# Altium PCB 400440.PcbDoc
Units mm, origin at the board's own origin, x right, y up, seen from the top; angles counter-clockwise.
Board outline 44.17 x 77.19 mm, 2 copper layers (Top Layer, Bottom Layer), stack 1.271 mm thick; 54 components, 42 nets, 195 pads, 342 vias.
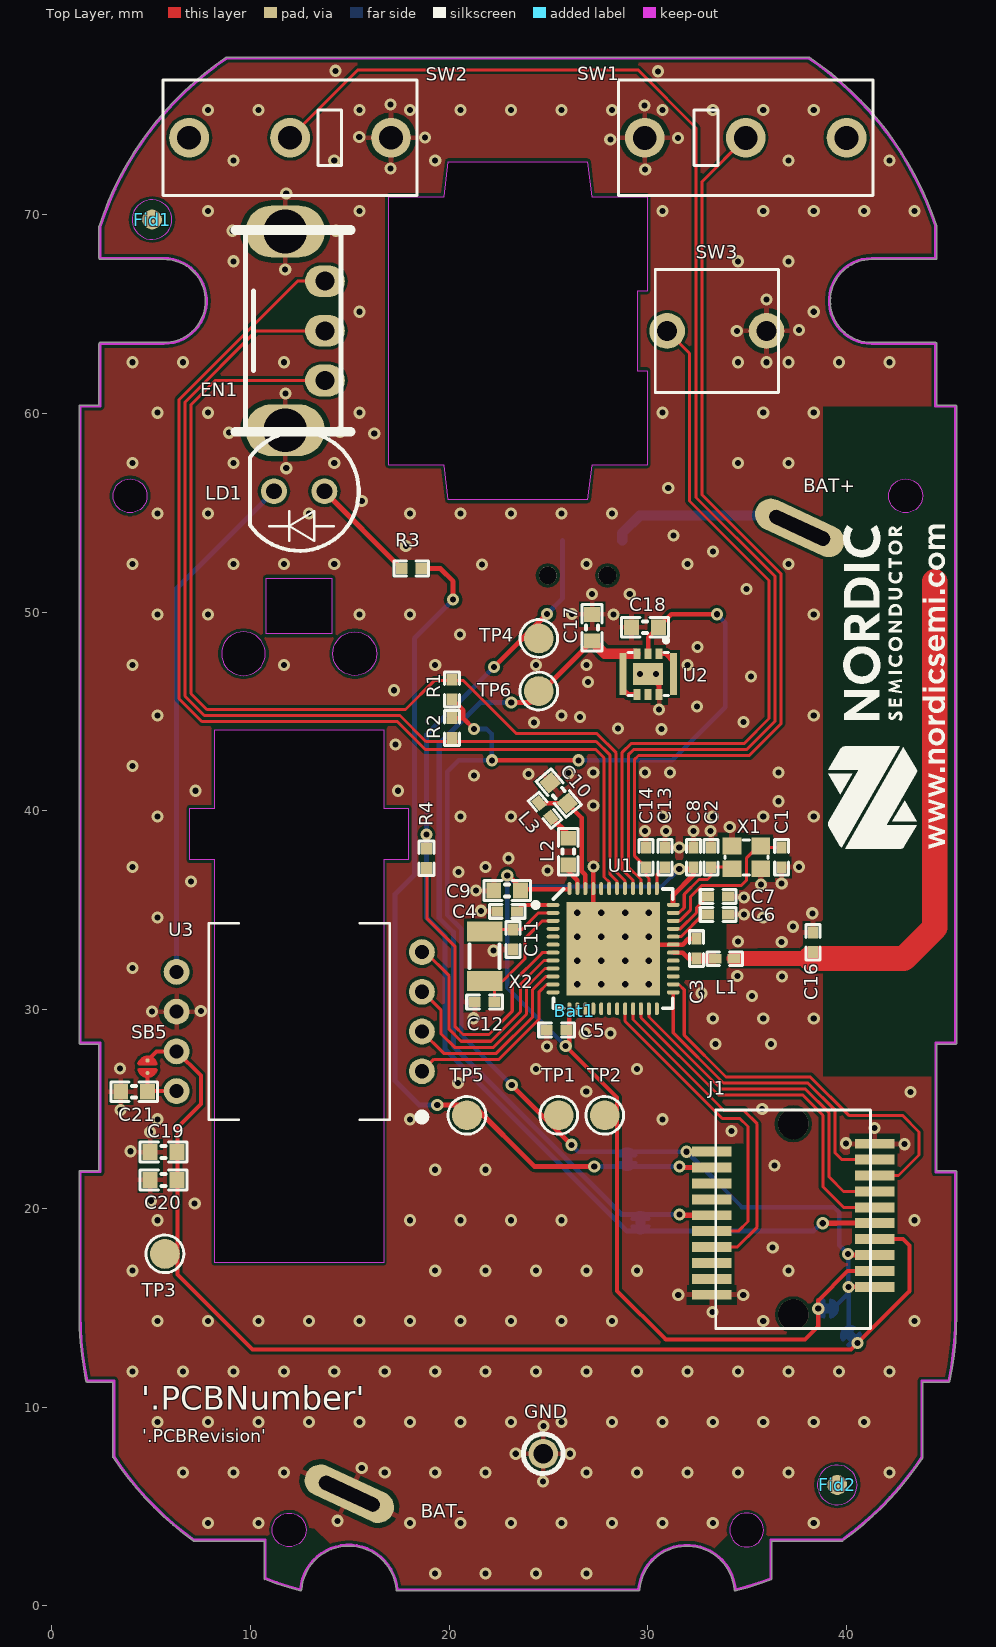
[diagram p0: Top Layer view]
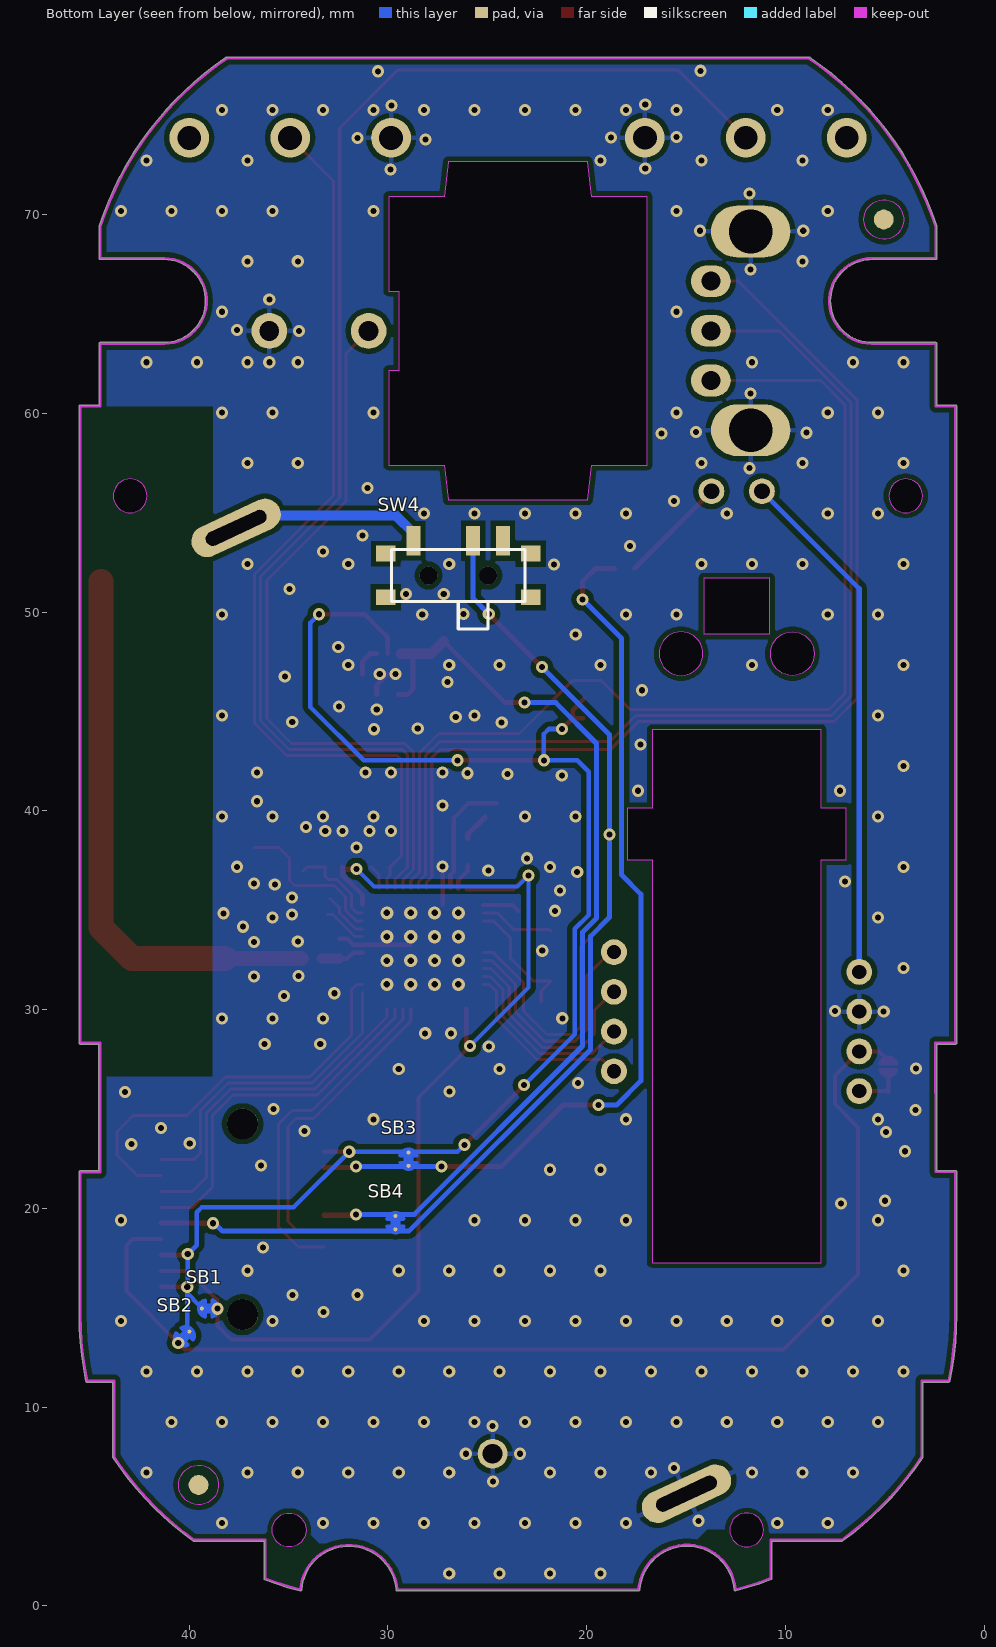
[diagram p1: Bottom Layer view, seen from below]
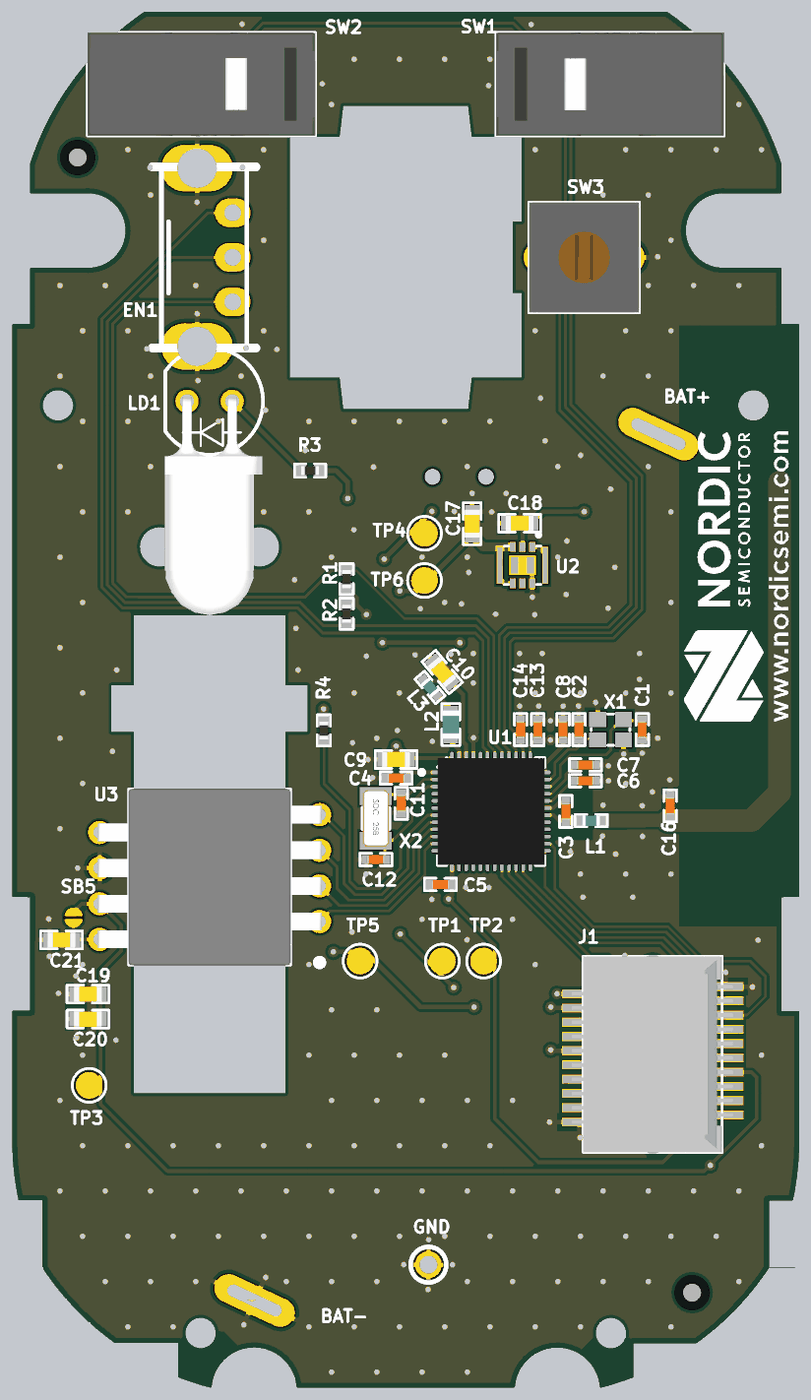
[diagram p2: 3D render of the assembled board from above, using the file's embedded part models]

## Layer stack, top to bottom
Top Solder: solder mask 0.0102, Solder Resist, Dk 3.5
Top Layer: signal copper 0.0356
Dielectric1: core 1.2, FR-4, Dk 4.8
Bottom Layer: signal copper 0.0356
Bottom Solder: solder mask 0.0102, Solder Resist, Dk 3.5

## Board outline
3.077,7.489 3.077,11.259 1.784,11.259 cw(c1.784,11.323) 1.721,11.31 cw(c17.452,14.626) 1.375,14.626 1.375,21.831 cw(c1.439,21.831) 1.439,21.895 2.376,21.895 2.376,28.266 1.445,28.266 cw(c1.445,28.33) 1.393,28.292 cw(c1.439,28.336) 1.375,28.336 1.375,60.362 cw(c1.439,60.362) 1.439,60.425 2.376,60.425 2.376,63.514 cw(c2.44,63.514) 2.44,63.578 5.643,63.578 ccw(c5.643,65.666) 7.731,65.666 ccw(c5.643,65.666) 5.616,67.753 ccw(c5.643,65.666) 5.616,67.753 cw(c5.615,67.817) 5.615,67.753 2.44,67.753 cw(c2.44,67.817) 2.376,67.817 2.376,69.412 cw(c2.44,69.412) 2.379,69.432 cw(c17.952,64.365) 8.775,77.928 cw(c8.811,77.875) 8.811,77.939 38.103,77.939 cw(c38.103,77.875) 38.139,77.928 cw(c28.961,64.365) 44.534,69.432 cw(c44.473,69.412) 44.537,69.412 44.537,67.817 cw(c44.473,67.817) 44.473,67.753 41.271,67.753 cw(c41.271,67.817) 41.27,67.753 ccw(c41.271,65.666) 41.271,63.578 44.473,63.578 cw(c44.473,63.514) 44.537,63.514 44.537,60.425 45.474,60.425 cw(c45.474,60.362) 45.526,60.399 ccw(c45.479,60.355) 45.526,60.399 cw(c45.479,60.355) 45.543,60.355 45.543,28.33 cw(c45.479,28.33) 45.479,28.266 44.542,28.266 44.542,21.889 45.479,21.889 cw(c45.479,21.825) 45.543,21.825 45.543,14.619 cw(c29.467,14.619) 45.198,11.303 cw(c45.135,11.317) 45.135,11.253 43.842,11.253 43.842,7.483 cw(c43.778,7.483) 43.831,7.447 cw(c30.425,16.321) 39.797,3.258 cw(c39.76,3.31) 39.76,3.246 36.236,3.246 36.236,1.375 cw(c36.172,1.375) 36.195,1.315 cw(c30.425,16.321) 34.428,0.75 cw(c34.412,0.812) 34.412,0.748 cw(c34.412,0.812) 34.348,0.807 ccw(c31.969,0.608) 29.589,0.808 cw(c29.525,0.814) 29.515,0.751 17.394,0.751 cw(c17.394,0.815) 17.33,0.81 ccw(c14.95,0.615) 12.57,0.814 ccw(c14.95,0.615) 12.57,0.813 12.57,0.814 cw(c12.507,0.819) 12.507,0.755 cw(c12.507,0.819) 12.491,0.757 cw(c16.493,16.327) 10.724,1.321 cw(c10.747,1.381) 10.683,1.381 10.683,3.253 7.159,3.253 cw(c7.159,3.317) 7.122,3.265 cw(c16.493,16.327) 3.087,7.454 cw(c3.141,7.489)
cut-out: 34.12,3.811 ccw(c34.971,3.811) 34.971,2.96 ccw(c34.971,3.811) 35.822,3.811 ccw(c34.971,3.811) 34.971,4.661 ccw(c34.971,3.811)
cut-out: 11.948,2.966 cw(c11.948,3.817) 11.097,3.817 cw(c11.948,3.817) 11.948,4.668 cw(c11.948,3.817) 12.798,3.817 cw(c11.948,3.817)
cut-out: 42.972,55.007 cw(c42.972,55.858) 42.121,55.858 cw(c42.972,55.858) 42.972,56.709 cw(c42.972,55.858) 43.823,55.858 cw(c42.972,55.858)
cut-out: 3.941,55.007 cw(c3.941,55.858) 3.091,55.858 cw(c3.941,55.858) 3.941,56.709 cw(c3.941,55.858) 4.792,55.858 cw(c3.941,55.858)
cut-out: 15.25,46.816 cw(c15.25,47.917) 14.149,47.917 cw(c15.25,47.917) 15.25,49.018 cw(c15.25,47.917) 16.351,47.917 cw(c15.25,47.917)
cut-out: 9.646,46.816 ccw(c9.646,47.917) 10.747,47.917 ccw(c9.646,47.917) 9.646,49.018 ccw(c9.646,47.917) 8.545,47.917 ccw(c9.646,47.917)
cut-out: 10.797,48.913 10.797,51.715 14.099,51.715 14.099,48.913
cut-out: 16.701,44.089 16.701,40.146 17.952,40.146 17.952,37.544 16.701,37.544 16.701,17.268 8.195,17.268 8.195,37.544 6.944,37.544 6.944,40.146 8.195,40.146 8.195,44.089
cut-out: 29.962,70.92 29.962,66.166 29.461,66.166 29.461,62.163 29.962,62.163 29.962,57.409 27.166,57.409 26.959,55.658 19.954,55.658 19.748,57.409 16.952,57.409 16.952,70.92 19.748,70.92 19.954,72.671 26.959,72.671 27.166,70.92

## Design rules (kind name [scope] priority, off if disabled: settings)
Clearance ANT_Clerance [InNet('ANT')] p1: gap=0.127 ignorepadtopadclearanceinfootprint=FALSE except(0: Arc-Hole Track-Hole SMDPad-Hole THPad-Hole Via-Hole Fill-Hole Poly-Hole Region-Hole Text-Hole)
Clearance Polygon_Clearance [(InNamedPolygon('Top_Layer-GND')) or (InNamedPolygon('Bottom_Layer-GND'))] p2: gap=0.254 ignorepadtopadclearanceinfootprint=FALSE except(0: Arc-Hole Track-Hole SMDPad-Hole THPad-Hole Via-Hole Fill-Hole Poly-Hole Region-Hole Text-Hole)
Clearance [All] p3: gap=0.152 ignorepadtopadclearanceinfootprint=FALSE except(0: Arc-Hole Track-Hole SMDPad-Hole THPad-Hole Via-Hole Fill-Hole Poly-Hole Region-Hole Text-Hole)
ComponentClearance [All] p1 off: gap=0.254 collisioncheckmode=3 verticalgap=0.254 showdistances=FALSE
DiffPairsRouting [All] p1: maxlimit=0.15 minlimit=0.15 mostfreqgap=0.15 toplayer_minwidth=0.381 toplayer_maxwidth=0.381 toplayer_prefwidth=0.381 bottomlayer_minwidth=0.381 bottomlayer_maxwidth=0.381 bottomlayer_prefwidth=0.381 maxuncoupledlength=12.7
FabricationTestPointUsage TestPointUsage [All] p1: valid=0 allowmultiple=FALSE
FabricationTestpoint Testpoint [All] p1: side=3 testpointundercomponent=TRUE minsize=1.016 maxsize=2.54 preferedsize=1.524 minholesize=0 maxholesize=1.016 preferedholesize=0.813 testpointgrid=0.025 allowsidetop=TRUE allowsidebottom=TRUE usegrid=TRUE gridtolerance=0
Height [All] p1 off: minheight=0 maxheight=25.4 prefheight=12.7
HoleSize [All] p1: absolutevalues=TRUE maxlimit=5 minlimit=0.305 maxpercent=80.000 minpercent=20.000
MinimumAnnularRing [All] p1 off: minimumring=0.152
PolygonConnect PolygonConnect_1 [isVia and innet(gnd)] p1: connectstyle=Direct reliefconductorwidth=0.254 reliefentries=4 polygonreliefangle="90 Angle" airgapwidth=0.254
PolygonConnect [All] p2: connectstyle=Relief reliefconductorwidth=0.254 reliefentries=4 polygonreliefangle="90 Angle" airgapwidth=0.254
RoutingVias [All] p1: holewidth=0.305 width=0.61 viastyle="Through Hole" minholewidth=0.305 minwidth=0.61 maxholewidth=0.711 maxwidth=1.27
SilkToSolderMaskClearance SilkscreenOverComponentPads [IsPad] p1: minsilkscreentomaskgap=0.254 clearancetoexposedcopper=TRUE
SolderMaskExpansion [All] p1: expansion=0.076 istentingtop=FALSE
Width [All] p1: maxlimit=2.54 minlimit=0.152 preferedwidth=0.152
23 further rules are at their usual default settings.

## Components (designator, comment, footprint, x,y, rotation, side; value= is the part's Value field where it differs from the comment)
Bat1 "" MORFFLUOA_Battery_Spring 26.308,29.943 r0 top locked
C1 "12pF" CAPC1005X04L 36.736,37.668 r270 top
C2 "12pF" CAPC1005X04L 33.18,37.668 r90 top
C3 "0.8pF" CAPC1005X04L 32.443,33.071 r270 top
C4 "100nF" CAPC1005X04L 22.918,34.95 r180 top
C5 "100nF" CAPC1005X04L 25.407,28.981 r180 top
C6 "N.C." CAPC1005X04L 33.535,34.798 r180 top
C7 "100pF" CAPC1005X04L 33.535,35.687 r0 top
C8 "100nF" CAPC1005X04L 32.291,37.668 r90 top
C9 "4.7µF" CAPC1608X06L 22.918,35.992 r180 top
C10 "1.0µF" CAPC1608X06L 25.51,40.899 r310 top
C11 "12pF" CAPC1005X04L 23.207,33.528 r270 top
C12 "12pF" CAPC1005X04L 21.785,30.378 r180 top
C13 "12pF" CAPC1005X04L 30.868,37.668 r90 top
C14 "12pF" CAPC1005X04L 29.903,37.668 r90 top
C16 "1.2pF" CAPC1005X04L 38.304,33.392 r90 top
C17 "10µF" CAPC1608X06L 27.19,49.222 r270 top
C18 "10µF" CAPC1608X06L 29.851,49.247 r0 top
C19 "10µF" CAPC1608X06L 5.627,22.831 r0 top
C20 "100nF" CAPC1608X06L 5.627,21.429 r0 top
C21 "4.7µF" CAPC1608X06L 4.145,25.869 r0 top
EN1 "Scroll wheel encoder" M01_Scroll_Wheel_Encoder 13.748,64.164 r270 top locked
Fid1 "Fiducial mark" Fiducial 5.048,69.766 r0 top
Fid2 "Fiducial mark" Fiducial 39.53,6.082 r0 top
GND "TP" TESTPAD-TH 24.733,7.649 r0 top
J1 "Card Edge, 0.8mm" 10056847-101LF 37.316,19.453 r90 top
L1 "3.9nH" INDC1005X04L 33.866,32.563 r0 top
L2 "10µH" INDC1608X06L 25.992,37.953 r270 top
L3 "15nH" INDC1005X04L 24.824,40.035 r310 top
LD1 "LED" LED_5MM_RA 12.452,56.09 r180 top locked
R1 "1M0" RESC1005X04L 20.136,46.111 r270 top
R2 "1M0" RESC1005X04L 20.136,44.17 r90 top
R3 "4R7" RESC1005X04L 18.093,52.202 r0 top
R4 "1k" RESC1005X04L 18.861,37.62 r270 top
SB1 "Solderbridge" Solderbridge_Shorted_Power 39.026,14.961 r180 bottom net-tie
SB2 "Solderbridge" Solderbridge_Shorted_Power 40.236,13.554 r315 bottom net-tie
SB3 "Solderbridge" Solderbridge_Shorted_Power 28.964,22.477 r270 bottom net-tie
SB4 "Solderbridge" Solderbridge_Shorted_Power 29.626,19.283 r90 bottom net-tie
SB5 "Solderbridge" Solderbridge 4.819,27.124 r270 top
SW1 "SPDT" D2F-F 29.842,73.875 r0 top locked
SW2 "SPDT" D2F-F 17.072,73.882 r180 top locked
SW3 "EVQ-P0E07K" EVQP0E07K 33.471,64.157 r0 top locked
SW4 "CUS-12TB" CUS-12B 26.462,51.853 r180 bottom locked
TP1 "Ø1.5mm,SMD" TP_SMD_Ø1.5mm 25.513,24.683 r0 top
TP2 "Ø1.5mm,SMD" TP_SMD_Ø1.5mm 27.828,24.683 r0 top
TP3 "Ø1.5mm,SMD" TP_SMD_Ø1.5mm 5.694,17.711 r0 top
TP4 "Ø1.5mm,SMD" TP_SMD_Ø1.5mm 24.512,48.683 r0 top
TP5 "Ø1.5mm,SMD" TP_SMD_Ø1.5mm 20.897,24.683 r0 top
TP6 "Ø1.5mm,SMD" TP_SMD_Ø1.5mm 24.512,46.033 r0 top
U1 "nRF52832-QFAAE0" QFN40P600X600X90-48N 28.252,33.071 r0 top locked
U2 "XCL101" CL-2025 30.014,46.889 r270 top
U3 "PAW3212" PAW3212DB-TJDT 12.454,28.899 r90 top locked
X1 "32MHz" BT-XTAL_2016 34.958,37.668 r180 top
X2 "32.768kHz" XTAL_3215 21.785,32.69 r270 top

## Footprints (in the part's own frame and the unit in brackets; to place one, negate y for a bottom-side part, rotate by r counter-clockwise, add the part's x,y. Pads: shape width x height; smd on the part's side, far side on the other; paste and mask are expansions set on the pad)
10056847-101LF [mm]
  rect 0.5x2 smd paste-0.05 mask+0.025: 1(-3.4,-4.1) 2(-2.6,-4.1) 3(-1.8,-4.1) 4(-1,-4.1) 5(-0.2,-4.1) 6(0.6,-4.1) 7(1.4,-4.1) 8(2.2,-4.1) 9(3,-4.1) 10(3.8,-4.1) 11(3.4,4.1) 12(2.6,4.1) 13(1.8,4.1) 14(1,4.1) 15(0.2,4.1) 16(-0.6,4.1) 17(-1.4,4.1) 18(-2.2,4.1) 19(-3,4.1) 20(-3.8,4.1)
  round 1.55 hole 1.55 unplated mask+0: ""(-4.8,0) ""(4.8,0)
  silkscreen extent -5.5,-3.9 5.5,3.9, body extent -5.5,-4.5 5.5,4.53, height 5.28
BT-XTAL_2016 [mm] "Crystal 2.0 x 1.6 mm"
  rect 0.95x0.85 smd: 1(-0.725,-0.575) 2(0.725,-0.575) 3(0.725,0.575) 4(-0.725,0.575)
  silkscreen extent -1.08,-0.88 1.08,0.88
CAPC1005X04L [mm] "Chip Capacitor, 2-Leads, Body 1.0x0.5mm, IPC High Density"
  rect 0.6x0.5 smd: 1(-0.5,0) 2(0.5,0)
  silkscreen extent -0.9,-0.35 0.9,0.35, body extent -0.51,-0.25 0.51,0.25, height 0.5
CAPC1608X06L [mm] "Chip Capacitor, 2-Leads, Body 1.6x0.8mm, IPC High Density"
  rect 0.75x0.8 smd: 1(-0.675,0) 2(0.675,0)
  silkscreen extent -1.17,-0.5 1.17,0.5, body extent -0.8,-0.43 0.8,0.43, height 0.8
CL-2025 [mm]
  rect 0.55x0.35 smd paste-0.025 mask+0.076: 1(-1.025,0.55) 2(-1.025,0) 3(-1.025,-0.55) 4(1.025,-0.55) 5(1.025,0) 6(1.025,0.55)
  rect 2.1x0.35 smd paste-0.038 mask+0.076: 7(0,1.275) 8(0,-1.275)
  rect 1.1x1.5 smd paste-5 mask+0.076: 9(0,0)
  silkscreen extent -1.8,-1.02 1.07,1.02, body extent -1,-1.25 1.01,1.25, height 1
CUS-12B [mm] "Slide Switches - SPDT, SMD, ON-ON"
  rect 1x0.8 smd: 0(-3.65,-1.1) 0(-3.65,1.1) 0(3.65,-1.1) 0(3.65,1.1)
  round 0.9 hole 0.9 unplated: 0(-1.5,0) 0(1.5,0)
  rect 0.7x1.5 smd: 1(2.25,1.75) 2(0.75,1.75) 3(-2.25,1.75)
  silkscreen extent -3.35,-2.7 3.35,1.3, body extent -3.85,-2.75 3.85,2.2, height 1.4
D2F-F [mm]
  round 2 hole 1.2: 1(10.16,0) 2(0,0) 3(5.08,0)
  silkscreen extent -1.32,-2.9 11.48,2.9, body extent -1.32,-2.9 11.48,2.9, height 7
EVQP0E07K [mm]
  round 1.8 hole 1: 1(-2.5,0) 2(2.5,0)
  silkscreen extent -3.1,-3.1 3.1,3.1, body extent -3.1,-3.1 3.1,3.1, height 7.5
Fiducial [mm] "Fiducial Mark"
  round 1 smd paste+0 mask+0.5: 0(0,0)
  round 1 smd far side paste+0 mask+0.5: 0(0,0)
  Top Layer keep-out circle w0.01: c0,0 r1
  Bottom Layer keep-out circle w0.01: c0,0 r1
INDC1005X04L [mm] "Chip Inductor, 2-Leads, Body 1.0x0.5mm, IPC High Density"
  rect 0.65x0.5 smd: 1(-0.475,0) 2(0.475,0)
  silkscreen extent -0.9,-0.35 0.9,0.35, body extent -0.5,-0.3 0.5,0.3, height 0.5
INDC1608X06L [mm] "Chip Inductor, 2-Leads, Body 1.6x0.8mm, IPC High Density"
  rect 0.75x0.8 smd: 1(-0.675,0) 2(0.675,0)
  silkscreen extent -1.18,-0.5 1.17,0.5, body extent -0.8,-0.48 0.8,0.48, height 0.8
LED_5MM_RA [mm]
  round 1.3 hole 0.8: 1(1.27,0) 2(-1.27,0)
  silkscreen extent -3,-3 2.48,3, body extent -2.95,-0.25 2.5,12, height 5.95
M01_Scroll_Wheel_Encoder [mm]
  oval 1.6x2 hole 0.95: 1(-2.5,0) 2(0,0) 3(2.5,0)
  oval 2.6x4 hole 2.2: 4(-5,-2) 5(5,-2)
  silkscreen extent -5.08,-4.5 5.08,1.3
MORFFLUOA_Battery_Spring [mm] "Edge Mount Battery Holder Suitable for 1xAAA"
  oval 4.8x1.6 hole 0.7 slot 3.3 at 155 deg rot 155: 1(11.333,24.304) 2(-11.333,-24.304)
PAW3212DB-TJDT [mm] "Ultra Low Power Wireless Mouse Sensor"
  round 1.3 hole 0.71: 1(-2,-6.172) 2(0,-6.172) 3(2,-6.172) 4(4,-6.172) 5(3,6.172) 6(1,6.172) 7(-1,6.172) 8(-3,6.172)
  silkscreen extent -4.55,-6.42 5.45,4.55, body extent -4.45,-6.3 5.45,6.3, height 3.18
QFN40P600X600X90-48N [mm] "QFN, 48-Leads, Body 6,0x6,0mm (max), Pitch 0,40mm, IPC Medium Density"
  oval 0.65x0.2 smd mask+0.05: 1(-3.025,2.2) 2(-3.025,1.8) 3(-3.025,1.4) 4(-3.025,1) 5(-3.025,0.6) 6(-3.025,0.2) 7(-3.025,-0.2) 8(-3.025,-0.6) 9(-3.025,-1) 10(-3.025,-1.4) 11(-3.025,-1.8) 12(-3.025,-2.2) 25(3.025,-2.2) 26(3.025,-1.8) 27(3.025,-1.4) 28(3.025,-1) 29(3.025,-0.6) 30(3.025,-0.2) 31(3.025,0.2) 32(3.025,0.6) 33(3.025,1) 34(3.025,1.4) 35(3.025,1.8) 36(3.025,2.2)
  oval 0.2x0.65 smd mask+0.05: 13(-2.2,-3.025) 14(-1.8,-3.025) 15(-1.4,-3.025) 16(-1,-3.025) 17(-0.6,-3.025) 18(-0.2,-3.025) 19(0.2,-3.025) 20(0.6,-3.025) 21(1,-3.025) 22(1.4,-3.025) 23(1.8,-3.025) 24(2.2,-3.025) 37(2.2,3.025) 38(1.8,3.025) 39(1.4,3.025) 40(1,3.025) 41(0.6,3.025) 42(0.2,3.025) 43(-0.2,3.025) 44(-0.6,3.025) 45(-1,3.025) 46(-1.4,3.025) 47(-1.8,3.025) 48(-2.2,3.025)
  rect 4.7x4.7 smd: 49(0,0)
  silkscreen extent -4.02,-3 3,3, body extent -3.02,-3.02 3.02,3.02, height 0.86
RESC1005X04L [mm] "Chip Resistor, 2-Leads, Body 1.0x0.5mm, IPC High Density"
  rect 0.6x0.55 smd: 1(-0.5,0) 2(0.5,0)
  silkscreen extent -0.87,-0.38 0.88,0.38, body extent -0.5,-0.25 0.5,0.25, height 0.3
Solderbridge [mm]
  round 0.2 smd paste-10: 1(-0.312,0) 2(0.312,0)
  Top Layer region: 0.077,0.432 0.152,0.505 0.271,0.467 0.335,0.424 0.409,0.351 0.462,0.292 0.521,0.193 0.549,0.099 0.544,-0.122 0.518,-0.193 0.434,-0.33 0.351,-0.411 0.259,-0.469 0.157,-0.5 0.107,-0.483 0.077,-0.43
  Top Layer region: -0.077,-0.432 -0.152,-0.505 -0.271,-0.467 -0.335,-0.424 -0.409,-0.351 -0.462,-0.292 -0.521,-0.193 -0.549,-0.099 -0.544,0.122 -0.518,0.193 -0.434,0.33 -0.351,0.411 -0.259,0.469 -0.157,0.5 -0.107,0.483 -0.077,0.43
  Top Layer lines w0.152: 0.153,-0.431 ccw(c0.042,0) 0.487,0.001 ccw(c0.042,0) 0.487,0.003 ccw(c0.042,0) 0.153,0.431 ; -0.153,-0.431 cw(c-0.042,0) -0.487,0 cw(c-0.042,0) -0.461,0.149 cw(c-0.042,0) -0.153,0.431
Solderbridge_Shorted_Power [mm]
  round 0.2 smd paste-10: 1(-0.338,0) 2(0.338,0)
  Top Layer region: -0.102,-0.432 -0.178,-0.505 -0.296,-0.467 -0.361,-0.424 -0.434,-0.351 -0.488,-0.292 -0.546,-0.193 -0.574,-0.099 -0.569,0.122 -0.544,0.193 -0.46,0.33 -0.376,0.411 -0.284,0.469 -0.183,0.5 -0.132,0.483 -0.102,0.43
  Top Layer region: 0.102,0.432 0.178,0.505 0.296,0.467 0.361,0.424 0.434,0.351 0.488,0.292 0.546,0.193 0.574,0.099 0.569,-0.122 0.544,-0.193 0.46,-0.33 0.376,-0.411 0.284,-0.469 0.183,-0.5 0.132,-0.483 0.102,-0.43
  Top Layer lines w0.152: 0.178,-0.431 ccw(c0.068,0) 0.178,0.431 ; -0.178,-0.431 cw(c-0.068,0) -0.178,0.431
  Top Layer lines w0.508: 0.338,0 -0.338,0
TESTPAD-TH [mm]
  round 1.5 hole 1: 1(0,0)
  silkscreen extent -1,-1 1,1
TP_SMD_Ø1.5mm [mm]
  round 1.5 smd paste-5: 1(0,0)
  silkscreen extent -0.95,-0.95 0.95,0.95
XTAL_3215 [mm] "XTAL SMD 3.2 x 1.5 mm"
  rect 1x1.8 smd: 1(-1.25,0) 2(1.25,0)
  silkscreen extent -0.6,-0.75 0.6,0.75, body extent -1.6,-0.75 1.6,0.75, height 0.81

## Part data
Bat1: library part "MORFFLOUA Battery Spring", "Battery Spring, 1xAA", Part number IPS=N.A.
C1 C2 C11 C12 C13 C14: library part C0402-12p, "Capacitor, NP0, ±2%"
C3: library part C0402-0.8p, "Capacitor, NP0, ±5%"
C4 C5 C8: library part C0402-100n, "Capacitor, X7R, ±10%"
C6: library part C0402-N.C., "Not mounted"
C7: library part C0402-100p, "Capacitor, NP0, ±5%"
C9: library part C0603-4µ7, "Capacitor, X5R, ±10%"
C10: library part C0603-1µ0, "Capacitor, X7R, ±10%"
C16: library part C0402-1.2p, "Capacitor, NP0, ±0.1pF", Manufacturer=N.A., Part number IPS=00000005410
C17 C18 C19: library part C0603-10µ, "Capacitor, X5R, ±20%", Part number IPS=00000007785
C20: library part C0603-100n, "Chip Cap 0603", Part number IPS=N.A.
C21: library part C0603-4µ7, "Capacitor, X5R, ±10%", Part number IPS=00000007783
EN1: library part "M01_Scroll_wheel_encoder, 9mm", "Scroll wheel encoder, 9mm", Part number IPS=N.A.
Fid1 Fid2: library part Fid-Mark, "Fiducial Mark", Part number IPS=N.A.
GND: library part "Testpoint TH", "Testpoint, through hole", Part number IPS=N.A.
J1: library part 10056847-101LF, "0.8mm pitch, dual edge, right angle, SMD, card edge connector", Manufacturer=FCI, Part number IPS=N.A., Supplier Part Number 1=609-4943-1-ND
L1: library part L0402-3n9, "High frequency chip inductor ±5%", Manufacturer=Murata, Manufacturer Part Number=LQP15MN3N9B02D, Supplier part number=490-1131-1-ND
L2: library part L0603-10µ, "Chip inductor, IDC,min = 50 mA, ±20%", 2nd source part number=178-6105, Manufacturer="Taiyo Yuden", Manufacturer Part Number=LBMF1608T100K, Supplier part number=587-1714-1-ND
L3: library part L0402-15n, "High frequency chip inductor ±10%", 2nd source part number=658-1328, Manufacturer="Taiyo Yuden", Manufacturer Part Number=HK100515NJ-T, Supplier part number=587-1521-1-ND
LD1: library part 7383M-RNW3-APSB, "LED, Red, 5mm, Vf=2.0", Manufacturer=Everlight, Part number IPS=N.A.
R1 R2: library part R0402-1M0, "Resistor, ±1%, 0.063W", Part number IPS=00000006807
R3: library part R0402-4R7, "Resistor, ±1%, 0.063W", Part number IPS=N.A.
R4: library part R0402-1k0, "Resistor, ±1%, 0.063W", Part number IPS=00000002218, Supplier Part Number 1=173-8850
SB1 SB2 SB3 SB4: library part "Solderbridge Shorted Power", "Shorted Solderbridge Power", Part number IPS=N.A.
SB5: Part number IPS=N.A.
SW1 SW2: library part D2F-F, "SWITCH SNAP ACTION SPDT 1A 125V", Manufacturer=Omron, Part number IPS=N.A., Supplier Part Number 1=SW503-ND
SW3: "Switch tactile, SPST-NO, 0.05A, 30V", Manufacturer="Panasonic - ECG", Part number IPS=N.A., Supplier Part Number 1=P10843S-ND
SW4: "Low-profile slide switch, SPDT, ON-ON", Manufacturer="Copal Electronics Inc", Part number IPS=N.A., Supplier Part Number 1=563-1102-1-ND
TP1 TP2 TP3 TP4 TP5 TP6: library part TP_SMD_Ø1.5MM, "1.0mm circular SMD testpad", Manufacturer="Nordic Semiconductor", Part number IPS=N.A.
U1: "Multi-protocol Bluetooth Low Energy, ANT and 2.4GHz proprietary system-on-chip", Manufacturer="Nordic Semiconductor", Part number IPS=N.A.
U2: library part XCL101A211ER-G, "Inductor Built-in Step-up “micro DC/DC” Converter, VOUT=2.1V, 100mA", Manufacturer="Torex Semiconductor", Part number IPS=N.A., Supplier Part Number 1=893-1206-1-ND
U3: library part PAW3212DB-TJDT, "Ultra Low Power Wireless Mouse Sensor", Manufacturer="Pixart Imaging inc", Part number IPS=N.A.
X1: library part XTAL_SMD2016_32MHz_8pF_General, "XTAL SMD 2016, 32MHz, Cl=8pF, Total Tol: ±40ppm"
X2: library part XTAL_SMD3215_32.768kHz_9pF_General, "XTAL SMD 3215, 32.768kHz, Cl=9pF, Total Tol: ±50ppm"

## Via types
v1: diameter 0.61, hole 0.305, Top Layer to Bottom Layer, tented both sides, 326 vias
v2: diameter 0.66, hole 0.33, Top Layer to Bottom Layer, tented both sides, 16 vias

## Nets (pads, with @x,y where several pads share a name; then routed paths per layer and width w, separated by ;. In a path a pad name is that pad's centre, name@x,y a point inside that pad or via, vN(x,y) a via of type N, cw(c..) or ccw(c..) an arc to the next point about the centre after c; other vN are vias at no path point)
ANT: C16.1 L1.2 | length 28.3
  Top Layer w0.762: L1.2@34.349,32.569 35.508,32.57 36.508,32.572 38.304,32.573
  Top Layer w1.27: 38.19,32.573 42.879,32.573 44.439,34.132 44.439,51.554
BAT+: Bat1.1 SW4.3 | length 9.9
  Bottom Layer w0.508: SW4.3 28.712,53.985 29.591,54.864 37.023,54.864 Bat1.1@37.641,54.246
DEC1: C4.1 U1.1 | length 1.9
  Top Layer w0.203: C4.1@23.422,34.97 23.723,35.271 U1.1
DEC2: C6.2 U1.32 | length 2.2
  Top Layer w0.152: U1.32 31.663,33.671 32.79,34.798 C6.2@33.053,34.798
DEC3: C7.1 U1.33 | length 2.4
  Top Layer w0.152: U1.33 31.632,34.071 32.443,34.882 32.443,35.133 C7.1@32.927,35.617
DEC4: C10.2 L3.1 U1.46 | length 6
  Top Layer w0.229: L3.1 C10.2@25.926,40.399 ; C10.2 26.677,39.648 26.677,36.962 26.852,36.787 U1.46@26.852,36.126
GND: Bat1.2 C1.2 C2.2 C3.1 C4.2 C5.2 C6.1 C7.2 C8.2 C9.2 C10.1 C11.2 C12.2 C13.2 C14.2 C16.2 C17.1 C18.1 C19.1 C20.1 C21.1 EN1.4 EN1.5 GND.1 J1.10 J1.20 SW1.2 SW2.2 SW3.2 U1.31 U1.45 U1.49 U2.6 U2.9 U3.6 X1.2 X1.4 | length 6.9
  Top Layer w0.229: U1.49@27.252,35.271 U1.45 v1@27.252,37.211 ; U1.49@28.87,33.274 31.751,33.274 32.038,33.561 C3.1@32.451,33.561
  Top Layer w0.254: U2.9 30.564,46.339 U2.6
  other v1: 19.298,1.622 21.838,1.622 24.378,1.622 26.918,1.622 7.868,4.162 10.408,4.162 18.028,4.162 20.568,4.162 23.108,4.162 25.648,4.162 28.188,4.162 30.728,4.162 33.268,4.162 38.348,4.162 14.375,4.277 24.715,6.25 6.598,6.702 9.138,6.702 11.678,6.702 16.758,6.702 19.298,6.702 21.838,6.702 26.918,6.702 29.458,6.702 31.998,6.702 34.538,6.702 37.078,6.702 42.158,6.702 15.6,6.933 23.35,7.65 26.082,7.65 24.747,9.05 5.328,9.242 7.868,9.242 10.408,9.242 12.948,9.242 15.488,9.242 18.028,9.242 20.568,9.242 23.108,9.242 25.648,9.242 28.188,9.242 30.728,9.242 33.268,9.242 35.808,9.242 38.348,9.242 40.888,9.242 4.058,11.782 6.598,11.782 9.138,11.782 11.678,11.782 14.218,11.782 16.758,11.782 19.298,11.782 21.838,11.782 24.378,11.782 26.918,11.782 29.458,11.782 31.998,11.782 34.538,11.782 37.078,11.782 39.618,11.782 42.158,11.782 5.328,14.322 7.868,14.322 10.408,14.322 12.948,14.322 15.488,14.322 18.028,14.322 20.568,14.322 23.108,14.322 25.648,14.322 28.188,14.322 35.808,14.322 43.428,14.322 33.25,14.775 31.527,15.65 34.799,15.638 4.058,16.862 19.298,16.862 21.838,16.862 24.378,16.862 26.918,16.862 29.458,16.862 37.078,16.862 36.282,18.025 5.328,19.402 18.028,19.402 20.568,19.402 23.108,19.402 25.648,19.402 43.428,19.402 7.193,20.25 4.994,20.384 19.298,21.942 21.838,21.942 36.38,22.15 3.969,22.875 42.917,23.229 39.975,23.275 4.944,23.85 34.2,23.885 41.414,24.053 5.328,24.482 18.028,24.482 30.728,24.482 3.45,24.95 35.753,25 43.225,25.858 26.9,25.875 20.442,26.31 24.378,27.022 29.458,27.022 3.425,27.047 24.925,28.143 33.408,28.27 36.202,28.27 26.825,28.811 28.125,28.811 21.226,29.566 33.268,29.562 35.808,29.562 38.348,29.562 5.05,29.901 7.5,29.925 35.237,30.683 32.7,30.825 36.75,31.675 34.5,31.7 4.058,32.102 22.234,32.968 36.736,33.4 34.538,33.425 37.3,34.175 5.328,34.642 35.808,34.642 34.831,34.798 38.275,34.85 21.597,34.976 34.831,35.636 21.343,35.992 35.694,36.302 36.736,36.347 7,36.453 20.476,36.93 24.95,37.013 4.058,37.182 21.838,37.182 37.6,37.19 27.262,37.211 22.994,37.617 31.579,38.168 29.852,38.989 30.919,38.989 32.291,38.989 33.154,38.989 34.119,39.192 5.328,39.722 20.568,39.722 23.108,39.722 30.728,39.722 33.268,39.722 35.808,39.722 38.348,39.722 27.252,40.284 36.583,40.488 7.243,41.016 17.418,41.016 21.251,41.785 23.985,41.859 26,41.9 27.252,41.935 29.852,41.935 31.122,41.935 36.583,41.935 4.058,42.262 17.296,43.35 30.694,44.115 28.5,44.15 28.5,44.15 24.275,44.45 34.817,44.475 26.589,44.724 5.328,44.802 25.648,44.802 38.348,44.802 30.564,45.105 32.465,45.25 17.218,46.075 26.995,46.488 35.192,46.775 29.614,46.889 30.414,46.889 4.058,47.342 11.678,47.342 19.298,47.342 24.378,47.342 26.918,47.342 31.998,47.342 32.5,48.25 20.55,48.875 5.328,49.882 7.868,49.882 15.488,49.882 18.028,49.882 28.275,49.882 38.348,49.882 26.189,49.913 27.19,50.926 29.087,50.926 34.958,51.166 21.65,52.4 4.058,52.422 9.138,52.422 11.678,52.422 14.218,52.422 26.918,52.422 31.998,52.422 37.078,52.422 33.275,53.055 17.816,53.325 31.284,53.865 5.328,54.962 7.868,54.962 12.948,54.962 18.028,54.962 20.568,54.962 23.108,54.962 25.648,54.962 28.188,54.962 15.6,55.591 31.025,56.261 11.8,57.25 4.058,57.502 9.138,57.502 14.218,57.502 34.538,57.502 37.078,57.502 16.228,59 8.928,59.037 14.499,59.075 5.328,60.042 7.868,60.042 15.488,60.042 30.728,60.042 35.808,60.042 38.348,60.042 11.755,61 4.058,62.582 6.598,62.582 11.678,62.582 34.538,62.582 35.971,62.582 37.078,62.582 39.618,62.582 42.158,62.582 34.475,64.157 37.6,64.2 15.488,65.122 38.348,65.122 35.971,65.736 11.748,67.257 9.138,67.662 34.538,67.662 37.078,67.662 9.1,69.2 14.302,69.2 7.868,70.202 15.488,70.202 30.728,70.202 35.808,70.202 38.348,70.202 40.888,70.202 43.428,70.202 11.8,71.075 29.865,72.275 17.05,72.325 9.138,72.742 14.218,72.742 19.298,72.742 37.078,72.742 42.158,72.742 28.108,73.8 31.525,73.872 18.775,73.9 15.475,73.925 7.868,75.282 10.408,75.282 15.488,75.282 18.028,75.282 20.568,75.282 23.108,75.282 25.648,75.282 28.188,75.282 30.728,75.282 33.268,75.282 35.808,75.282 38.348,75.282 29.825,75.5 17.05,75.55 30.5,77.225 14.275,77.25
  other v2: 26.452,31.271 27.652,31.271 28.852,31.271 30.052,31.271 26.452,32.471 27.652,32.471 28.852,32.471 30.052,32.471 26.452,33.671 27.652,33.671 28.852,33.671 30.052,33.671 26.452,34.871 27.652,34.871 28.852,34.871 30.052,34.871
NetC3_2: C3.2 L1.1 U1.30 | length 2.2
  Top Layer w0.229: U1.30 31.752,32.871 32.062,32.561 C3.2@32.451,32.561
  Top Layer w0.508: C3.2@32.443,32.566 L1.1@33.34,32.566
NetC13_1: C13.1 U1.37 | length 1.3
  Top Layer w0.152: U1.37 30.452,36.795 30.847,37.19 C13.1
NetC21_2: C21.2 SB5.2 U3.8 | length 2.4
  Top Layer w0.203: SB5.2 4.82,26.637 C21.2 4.849,25.899 U3.8
NetL2_1: L2.1 L3.2 | length 1.4
  Top Layer w0.279: L3.2 25.992,38.809 L2.1
NetL2_2: L2.2 U1.47 | length 1.4
  Top Layer w0.229: L2.2 25.992,36.976 26.452,36.516 U1.47
NetLD1_1: LD1.1 U3.5 | length 26.2
  Bottom Layer w0.254: U3.5 6.282,51.19 LD1.1
NetLD1_2: LD1.2 R3.1 | length 5.5
  Top Layer w0.254: LD1.2 13.722,56.072 R3.1
NetU2_1: U2.1 U2.7 | length 1.5
  Top Layer w0.254: U2.1 30.895,47.914 31.289,47.52 U2.7
P0.00/XL1: C11.1 U1.2 X2.1 | length 3.8
  Top Layer w0.152: X2.1 21.873,34.028 C11.1 23.658,34.028 24.5,34.871 U1.2
P0.01/XL2: C12.1 U1.3 X2.2 | length 6.6
  Top Layer w0.152: C12.1 22.285,30.94 X2.2 22.69,31.44 23.825,32.575 23.825,33.596 24.7,34.471 U1.3
P0.05/AIN3: R4.2 U1.7 | length 16.3
  Top Layer w0.152: R4.2@18.836,37.12 R4.2@18.875,37.081 ; R4.2@18.875,37.12 R4.2@18.875,37.081 ; 24.671,32.871 24.696,32.871 ; U1.7 24.696,32.871 ; R4.2@18.875,37.081 18.875,34.6 20.305,33.17 20.305,29.136 20.691,28.75 22,28.75 23.175,29.925 23.175,31.35 24.696,32.871
P0.06: U1.8 U3.4 | length 12.5
  Top Layer w0.152: U3.4 18.801,32.899 20,31.7 20,29.01 20.6,28.41 22.104,28.41 23.59,29.896 23.59,31.289 24.772,32.471 U1.8
P0.07: U1.9 U3.3 | length 10.9
  Top Layer w0.152: U3.3 18.67,30.899 19.6,29.969 19.6,28.78 20.275,28.105 22.23,28.105 23.895,29.77 23.895,31.145 24.821,32.071 U1.9
P0.08: U1.10 U3.2 | length 9.5
  Top Layer w0.152: U3.2 19.725,27.8 22.369,27.8 24.2,29.631 24.2,31.013 24.857,31.671 U1.10
P0.09: U1.11 U3.1 | length 9.2
  Top Layer w0.152: U3.1 19.227,27.5 19.593,27.5 19.598,27.495 22.495,27.495 24.531,29.531 24.531,30.906 24.896,31.271 U1.11
P0.17: J1.16 U1.20 | length 15.8
  Top Layer w0.152: U1.20 28.852,29.423 33.75,24.525 34.627,24.525 35.035,24.117 35.035,19.335 34.553,18.853 J1.16
P0.18: J1.17 U1.21 | length 16.9
  Top Layer w0.152: U1.21 29.252,29.5 33.827,24.925 34.827,24.925 35.5,24.252 35.5,19.051 34.502,18.053 J1.17
P0.19: J1.6 U1.22 | length 18.3
  Top Layer w0.152: U1.22 29.652,29.6 33.552,25.7 37.8,25.7 38.818,24.682 38.818,21.082 39.847,20.053 J1.6
P0.20: J1.7 U1.23 | length 17.3
  Top Layer w0.152: U1.23 30.052,29.631 33.678,26.005 37.926,26.005 39.123,24.808 39.123,21.577 39.847,20.853 J1.7
P0.26: C14.1 SW1.3 U1.38 | length 47
  Top Layer w0.152: U1.38 30.052,36.605 29.903,36.754 C14.1 29.319,37.753 29.319,42.582 29.527,42.79 35.103,42.79 36.71,44.397 36.71,51.921 32.73,55.901 32.73,71.683 SW1.3
P0.27: SW2.3 U1.39 | length 69.6
  Top Layer w0.152: SW2.3 15.41,77.3 29.5,77.3 32.425,74.375 32.425,55.775 36.405,51.795 36.405,44.524 34.976,43.095 29.287,43.095 29.014,42.822 29.014,37.184 29.652,36.546 U1.39
P0.28/AIN4: SW3.1 U1.40 | length 36.8
  Top Layer w0.152: U1.40 29.252,36.515 28.709,37.058 28.709,42.948 29.161,43.4 34.85,43.4 36.1,44.65 36.1,51.6 32.099,55.601 32.099,63.029 SW3.1
P0.29/AIN5: EN1.3 R1.1 U1.41 | length 52.6
  Top Layer w0.152: EN1.3 8.226,61.664 7.01,60.447 7.01,45.903 7.803,45.11 8.421,45.11 8.426,45.105 17.805,45.105 19.275,46.575 20.7,46.575 23.375,43.9 27.431,43.9 28.405,42.927 28.405,36.932 28.852,36.484 U1.41
P0.30/AIN6: EN1.2 R2.1 U1.42 | length 52.8
  Top Layer w0.152: EN1.2 10.295,64.164 6.705,60.574 6.705,45.776 7.676,44.805 8.295,44.805 8.3,44.8 17.526,44.8 18.826,43.5 19.696,43.5 20.283,43.5 21.383,43.5 27.4,43.5 28.1,42.8 28.1,36.805 28.452,36.453 U1.42
P0.31/AIN7: EN1.1 U1.43 | length 54.2
  Top Layer w0.152: EN1.1 12.364,66.664 6.4,60.7 6.4,45.65 7.55,44.5 8.169,44.5 8.174,44.495 17.4,44.495 18.812,43.083 27.386,43.083 27.795,42.674 27.795,36.679 28.052,36.422 U1.43
SWDCLK: J1.9 U1.25 | length 16.1
  Top Layer w0.152: U1.25 31.277,28.837 33.805,26.31 38.053,26.31 39.428,24.934 39.428,22.791 39.766,22.453 J1.9
SWDIO: J1.8 U1.26 | length 20.6
  Top Layer w0.152: U1.26 31.567,31.271 31.831,31.007 31.831,28.715 33.931,26.614 38.179,26.614 40.111,24.683 42.811,24.683 43.647,23.847 43.647,22.689 42.611,21.653 J1.8
VBAT: C17.2 J1.15 SB4.2 TP6.1 U2.3 U2.4 U2.8 | length 46.9
  Top Layer w0.254: v1(23.125,45.45) 24.094,45.45 C17.2 ; U2.8@28.739,47.914 U2.8 28.739,46.131 29.006,45.864 U2.4 ; v1(31.6,19.7) 31.647,19.653 J1.15
  Top Layer w0.508: C17.2 27.824,47.914 28.739,47.914 U2.3@29.375,47.914
  Bottom Layer w0.254: v1(23.125,45.45) 21.55,45.45 19.5,43.4 19.5,34.606 20.206,33.9 20.206,28.168 28.675,19.7 29.386,19.7 29.866,19.7 v1(31.6,19.7)
VBAT_SW: J1.5 R4.1 SB4.1 SW4.2 TP4.1 | length 55
  Top Layer w0.254: v1@18.85,38.74 18.861,38.729 R4.1 ; v1(22.25,47.238) v1(24.925,49.913) ; v1(38.8,19.25) 39.499,19.25 39.502,19.253 J1.5
  Bottom Layer w0.254: v1(22.25,47.238) 18.875,43.863 18.85,43.838 v1(18.85,38.825) 18.85,34.65 18.875,34.625 19.8,33.7 19.8,28 28.947,18.853 29.409,18.853 29.843,18.853 38.328,18.853 38.725,19.25 v1(38.8,19.25) ; v1(24.925,49.913) 25.712,50.7 SW4.2
VDD_LED: J1.12 R3.2 SB3.2 TP5.1 | length 46
  Top Layer w0.254: R3.2 18.595,52.2 19.554,52.2 20.2,51.554 v1(20.2,50.64) ; v1(19.4,25.2) 21.19,25.2 21.195,25.205 24.3,22.1 v1(27.3,22.1) ; v1(31.6,22.1) 31.647,22.053 J1.12
  Bottom Layer w0.254: v1(19.4,25.2) 18.488,25.2 17.272,26.416 17.272,35.814 18.25,36.792 18.25,48.69 v1(20.2,50.64) ; v1(27.3,22.1) 28.671,22.1 29.257,22.1 v1(31.6,22.1)
VDD_nRF: C5.1 C8.1 C9.1 J1.2 SB1.2 TP2.1 U1.13 U1.36 U1.48 | length 57
  Top Layer w0.203: v1(25.865,28.169) 28.452,25.581 28.452,15.848 30.9,13.4 31.9,13.4 37.9,13.4 38.575,14.075 38.575,15.375 40.053,16.853 J1.2
  Top Layer w0.229: v1(22.922,36.748) 23.005,36.748 23.682,36.071 U1.48@26.042,36.071 ; v1(25.865,28.169) 26.052,28.356 U1.13
  Top Layer w0.254: U1.36@31.275,35.298 31.275,35.759 32.291,36.775 C8.1@32.291,37.067 ; v1(31.579,37.084) 31.597,37.067 C8.1@32.291,37.067 ; C8.1 C8.1@32.291,37.067
  Bottom Layer w0.203: v1(25.865,28.169) 22.922,31.111 v1(22.922,36.748) 23.47,36.2 30.695,36.2 v1(31.579,37.084)
  other v1: 38.575,14.95
VDD_Sensor: C19.2 C20.2 J1.4 SB2.2 SB5.1 TP3.1 U3.7 | length 57.7
  Top Layer w0.203: SB5.1 4.968,27.585 5.281,27.899 U3.7 7.5,26.681 7.5,25.248 6.333,24.081 6.333,16.667 10.1,12.9 40.229,12.9 v1(40.554,13.225) 43.158,15.829 43.158,18.142 42.847,18.453 J1.4
VREG: C18.2 J1.1 J1.3 J1.11 R1.2 R2.2 SB1.1 SB2.1 SB3.1 TP1.1 U2.2 | length 77.4
  Top Layer w0.229: R1.2@20.163,45.611 20.707,45.067 20.707,44.67 ; R2.2@20.171,44.67 20.707,44.67 ; v1@21.221,44.127 v1(21.25,44.127) ; v1@21.25,44.156 v1(21.25,44.127) ; v1@22.25,42.55 v1(26.5,42.55) ; v1(23.15,26.2) v1(26.15,23.2) ; U2.2 30.014,48.735 C18.2 31.176,49.897 32.805,49.897 32.808,49.9 v1(33.475,49.9) ; v1(31.95,22.85) 33.212,22.85 J1.11 ; v1(40.075,17.7) 40.122,17.653 J1.3 ; v1(40.1,16.05) 40.103,16.053 J1.1 ; 20.707,44.67 v1(21.25,44.127)
  Bottom Layer w0.229: v1@21.075,44.125 21.9,44.125 22.15,43.875 v1(22.15,42.55) 20.475,42.55 19.9,41.975 19.9,34.763 20.6,34.063 20.6,28.75 v1(23.15,26.2) ; v1(26.15,23.2) 26.5,22.85 28.667,22.85 29.261,22.85 v1(31.95,22.85) 34.734,20.066 39.359,20.066 39.625,19.8 39.625,18.15 v1(40.075,17.7) 40.075,16.075 v1(40.1,16.05) 40.1,15.722 ; v1(26.5,42.55) 31.225,42.55 33.9,45.225 33.9,49.475 v1(33.475,49.9) ; SB1.1@39.339,14.961 39.488,15.11 40.1,15.722 ; SB2.1@40.015,13.775 40.1,13.86 40.1,14.016 40.1,15.722
XC1: C1.1 U1.34 X1.1 | length 8
  Top Layer w0.152: U1.34 31.601,34.471 32.136,35.005 32.136,35.674 32.708,36.246 34.704,36.246 34.958,36.5 34.958,37.618 35.508,38.168 C1.1
XC2: C2.1 U1.35 X1.3 | length 4.7
  Top Layer w0.152: U1.35 31.567,34.871 31.831,35.135 31.831,35.803 32.578,36.551 33.002,36.551 33.179,36.728 C2.1@33.179,37.161 ; C2.1@33.129,37.168 34.085,37.168 X1.3@34.285,36.968
pads on no net: Fid1.0 Fid2.0 J1. J1.13 J1.14 J1.18 J1.19 SW1.1 SW2.1 SW4.0 SW4.1 U1.4 U1.5 U1.6 U1.12 U1.14 U1.15 U1.16 U1.17 U1.18 U1.19 U1.24 U1.27 U1.28 U1.29 U1.44 U2.5

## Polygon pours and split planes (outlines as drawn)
GND on Top Layer "Top Layer-GND" (solid, remove dead copper, pour order 41): 1.439,14.626 1.439,21.831 2.44,21.831 2.44,28.336 1.439,28.336 1.439,60.362 2.44,60.362 2.44,63.514 5.643,63.514 ccw(c5.643,65.666) 5.615,67.817 2.44,67.817 2.44,69.412 cw(c17.952,64.365) 8.811,77.875 38.103,77.875 cw(c28.961,64.365) 44.473,69.412 44.473,67.817 41.271,67.817 ccw(c41.271,65.666) 41.271,63.514 44.473,63.514 44.473,60.362 45.474,60.362 45.474,28.336 45.474,0.815 17.394,0.815 ccw(c14.95,0.615) 12.507,0.819 cw(c16.493,16.327) 10.747,1.381 10.747,3.317 7.159,3.317 cw(c16.494,16.327) 3.141,7.489 3.141,11.323 1.784,11.323 cw(c17.452,14.626)
GND on Bottom Layer "Bottom_Layer-GND" (solid, remove dead copper, pour order 42): 1.439,14.626 1.439,21.831 2.44,21.831 2.44,28.336 1.439,28.336 1.439,60.362 2.44,60.362 2.44,63.514 5.643,63.514 ccw(c5.643,65.666) 5.615,67.817 2.44,67.817 2.44,69.412 cw(c17.952,64.365) 8.811,77.875 38.103,77.875 cw(c28.961,64.365) 44.473,69.412 44.473,67.817 41.271,67.817 ccw(c41.271,65.666) 41.271,63.514 44.473,63.514 44.473,60.362 45.474,60.362 45.474,28.336 45.474,0.815 17.394,0.815 ccw(c14.95,0.615) 12.507,0.819 cw(c16.493,16.327) 10.747,1.381 10.747,3.317 7.159,3.317 cw(c16.494,16.327) 3.141,7.489 3.141,11.323 1.784,11.323 cw(c17.452,14.626)

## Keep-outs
Keep-Out Layer:
  lines w0.013: 22.456,0.815 17.394,0.815 ccw(c14.95,0.615) 12.507,0.819 cw(c16.493,16.327) 10.747,1.381 10.747,3.317 7.159,3.317 cw(c16.493,16.327) 3.141,7.489 3.141,11.323 1.784,11.323 cw(c17.452,14.626) 1.439,14.626 1.439,21.831 2.44,21.831 2.44,28.336 1.439,28.336 1.439,60.362 2.44,60.362 2.44,63.514 5.643,63.514 ccw(c5.643,65.666) 5.615,67.817 2.44,67.817 2.44,69.412 cw(c17.952,64.365) 8.811,77.875 38.103,77.875 cw(c28.961,64.365) 44.473,69.412 44.473,67.817 41.271,67.817 ccw(c41.271,65.666) 41.271,63.514 44.473,63.514 44.473,60.362 45.474,60.362 45.474,28.336 44.473,28.336
  lines w0.127: 1.445,60.355 1.445,28.33 2.446,28.33 2.446,25.828 ; 22.454,0.815 29.519,0.815 ; 29.525,0.814 cw(c31.969,0.608) 34.412,0.812 ccw(c30.425,16.321) 36.172,1.375 36.172,3.31 39.76,3.31 ccw(c30.425,16.321) 43.778,7.483 43.778,11.317 45.135,11.317 ccw(c29.467,14.619) 45.479,14.619 45.479,21.825 44.479,21.825 44.479,28.33 45.479,28.33 45.479,60.355 ; 45.474,28.336 45.474,60.362 ; 1.439,14.626 ccw(c17.452,14.626) 1.784,11.323 ; 1.439,14.626 ccw(c17.452,14.626) 1.784,11.323 ; 1.439,14.626 1.439,21.831 ; 1.439,14.626 1.439,21.831 ; 1.439,21.831 2.44,21.831 ; 1.439,21.831 2.44,21.831 ; 1.439,28.336 1.439,60.362 ; 1.439,28.336 2.44,28.336 ; 1.439,28.336 1.439,60.362 ; 1.439,28.336 2.44,28.336 ; 1.439,60.362 2.44,60.362 ; 1.439,60.362 2.44,60.362 ; 1.784,11.323 3.141,11.323 ; 2.44,21.831 2.44,28.336 ; 2.44,21.831 2.44,28.336 ; 2.44,60.362 2.44,63.514 ; 2.44,60.362 2.44,63.514 ; 2.44,63.514 5.643,63.514 ; 2.44,63.514 5.643,63.514 ; 2.44,67.817 2.44,69.412 ; 2.44,67.817 5.615,67.817 ; 2.44,67.817 2.44,69.412 ; 2.44,67.817 5.615,67.817 ; 2.44,69.412 cw(c17.952,64.365) 8.811,77.875 ; 2.44,69.412 cw(c17.952,64.365) 8.811,77.875 ; 3.141,7.489 ccw(c16.493,16.327) 7.159,3.317 ; 3.141,7.489 ccw(c16.493,16.327) 7.159,3.317 ; 3.141,7.489 3.141,11.323 ; 3.141,7.489 3.141,11.323 ; 5.615,67.817 cw(c5.643,65.666) 5.643,63.514 ; 5.615,67.817 cw(c5.643,65.666) 5.643,63.514 ; 7.159,3.317 7.159,3.317 ; 7.159,3.317 10.747,3.317 ; 7.159,3.317 10.747,3.317 ; 8.811,77.875 38.103,77.875 ; 8.811,77.875 38.103,77.875 ; 10.747,1.381 ccw(c16.493,16.327) 12.507,0.819 ; 10.747,1.381 ccw(c16.493,16.327) 12.507,0.819 ; 10.747,1.381 10.747,3.317 ; 10.747,1.381 10.747,3.317 ; 12.507,0.819 cw(c14.95,0.615) 17.394,0.815 ; 12.507,0.819 cw(c14.95,0.615) 17.394,0.815 ; 12.507,0.819 12.507,0.819 ; 17.394,0.815 22.456,0.815 17.394,0.815 ; 38.103,77.875 cw(c28.961,64.365) 44.473,69.412 ; 38.103,77.875 cw(c28.961,64.365) 44.473,69.412 ; 41.271,63.514 cw(c41.271,65.666) 41.271,67.817 ; 41.271,63.514 cw(c41.271,65.666) 41.271,67.817 ; 41.271,63.514 44.473,63.514 ; 41.271,63.514 44.473,63.514 ; 41.271,67.817 41.271,67.817 ; 41.271,67.817 44.473,67.817 ; 41.271,67.817 44.473,67.817 ; 44.473,60.362 45.474,60.362 ; 44.473,60.362 44.473,63.514 ; 44.473,60.362 45.474,60.362 ; 44.473,60.362 44.473,63.514 ; 44.473,67.817 44.473,69.412 ; 44.473,67.817 44.473,69.412

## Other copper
Top Layer:
  pour cut-out: 12.75,3.904 13.221,3.904 14.375,2.75 14.05,2.425 13.35,2.425 12.175,3.6
  pour cut-out: 34.119,3.675 33.119,2.675 32.85,2.675 32.85,2.625 33.35,2.125 34.65,3.425 34.922,3.425
  pour cut-out: 34.25,23.25 35.15,23.25 35.173,23.273 35.173,22.925 34.15,22.925 34.1,22.975
  pour cut-out: 14.525,66.025 14.475,65.975 14.475,64.739 13.907,64.739 13.746,64.9 13.775,64.929 13.775,66.183
  pour cut-out: 23.05,29.663 22.596,30.117 22.617,30.117 22.85,30.35 23.275,29.925 23.275,29.85
  pour cut-out: 33.967,31.471 31.224,31.471 31.224,34.366 33.967,34.366
Bottom Layer:
  pour cut-out: 32.775,3.15 33.45,3.15 34.3,4 34.725,3.575 34.725,3.05 33.702,3.05 32.827,2.175
  pour cut-out: 14.6,3.175 13.925,3.85 12.711,3.85 12.711,3.785 12.526,3.6 13.651,2.475 14.325,2.475
Multi-Layer:
  pour cut-out: 38.803,60.355 46.515,60.355 46.487,26.621 38.806,26.621

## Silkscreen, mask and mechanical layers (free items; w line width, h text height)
Top Overlay:
  drawing of 43 lines, arcs and shapes, not listed
  text "'.PCBNumber'" at 4.496,9.461 h2.03
  text "'.PCBRevision'" at 4.547,8.241 h0.64
Board Outline:
  drawing of 176 lines, arcs and shapes, not listed
Bottom Component Info:
  drawing of 267 lines, arcs and shapes, not listed
Bottom Assembly:
  circle w0.013: c40,73.872 r0.55
  circle w0.013: c29.832,73.872 r0.55
  circle w0.013: c34.916,73.872 r0.55
  circle w0.013: c17.082,73.872 r0.55
  circle w0.013: c6.914,73.872 r0.55
  circle w0.013: c11.998,73.872 r0.55
  circle w0.013: c13.749,66.667 r0.5
  circle w0.013: c13.749,64.165 r0.5
  circle w0.013: c13.749,61.663 r0.5
  circle w0.013: c11.747,68.668 r0.5
  circle w0.013: c11.747,59.661 r0.5
  circle w0.013: c6.271,25.894 r0.4
  circle w0.013: c6.271,31.899 r0.4
  circle w0.013: c6.271,29.898 r0.4
  circle w0.013: c6.271,27.896 r0.4
  circle w0.013: c18.625,26.895 r0.4
  circle w0.013: c18.625,28.897 r0.4
  circle w0.013: c18.625,30.898 r0.4
  circle w0.013: c18.625,32.9 r0.4
  circle w0.013: c13.639,56.089 r0.356
  circle w0.013: c11.257,56.089 r0.356
  circle w0.013: c24.958,51.855 r0.45
  circle w0.013: c27.96,51.855 r0.45
  circle w0.013: c36.007,64.165 r0.4
  circle w0.013: c30.923,64.165 r0.4
  lines w0.013: 3.025,68.861 2.494,69.123 3.287,70.862 3.877,70.571 ; 11.254,3.417 7.168,3.417 6.478,4.217 11.254,4.217 ; 11.547,3.124 11.547,1.239 12.348,0.996 12.348,3.124 ; 16.893,36.793 16.866,35.411 18.89,34.143 19.915,33.501 ; 34.571,3.117 34.571,0.99 35.371,1.233 35.371,3.117 ; 35.664,3.41 39.751,3.41 40.441,4.211 35.664,4.211 ; 43.036,70.571 43.656,70.877 44.45,69.138 43.888,68.861 ; 7.794,56.617 15.761,56.606 15.739,49.515 16.863,49.518 16.853,53.288 16.838,57.682 7.794,57.67 7.794,56.617 ; 13.652,5.865 cw(c13.8,6.182) 13.948,6.5 16.307,5.4 cw(c16.159,5.082) 16.011,4.765 13.652,5.865 ; 23.056,46.358 23.857,46.358 23.857,47.959 23.056,47.959 23.056,46.358 ; 36.323,54.481 cw(c36.471,54.798) 36.619,55.116 38.977,54.016 cw(c38.829,53.699) 38.681,53.381 36.323,54.481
